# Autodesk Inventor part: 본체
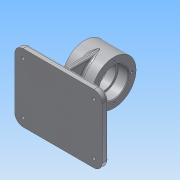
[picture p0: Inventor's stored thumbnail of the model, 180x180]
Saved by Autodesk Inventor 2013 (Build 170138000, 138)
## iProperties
Created: 2019-09
Part Number: 본체
Material: 알루미늄 6061
Document SubType Name: Modeling
Designer: Administrator
Density: 2.71 g/cm^3
Mass: 556.673 g
Surface Area: 495.884 cm^2
Volume: 205.414 cm^3
Author: Administrator
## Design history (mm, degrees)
sketch "스케치1"
  geometry: L1 (-21, 0)-(21, 0); L2 (-21, 0)-(-21, 32); L3 (-21, 32)-(21, 32); L4 (21, 32)-(21, 0); L5 (-21, 21)-(-6, 21); L6 (-6, 21)-(-6, 18); L7 (-6, 18)-(6, 18); L8 (6, 18)-(6, 21); L9 (6, 21)-(21, 21); L10 (-63, -50)-(63, -50); L11 (63, -50)-(63, -59); L12 (63, -59)-(-63, -59); L13 (-63, -59)-(-63, -50); 3 further points
  constraints: 26 end point, 6 perpendicular, 5 parallel, 2 coincident, 2 equal length, 2 horizontal, 2 midpoint, 2 point on line, 1 vertical alignment
  dimensions: "d0" = 64 diameter of L3 L1; "d2" = 42 diameter of L9 L1; "d3" = 36 diameter of L7 L1; "d4" = 15 distance of L5.start L5.end; "d5" = 42 distance of L2.end L3.end; "d6" = 9 distance of L10.end L11.end; "d7" = 59 distance from line of point (0, 0) L12; "d8" = 126 distance of L11.end L12.end
revolve "회전1" stored, may be unused: angle "d9" = 90 deg
extrude "돌출1" join sketch "스케치1" distance "d10" = 36; taper "d12" = 0 deg; dims "d11" = 62, "d13" = 0
sketch "스케치4"
  geometry: L1 (59, 68)-(67, 68); L2 (67, 68)-(67, 4); L3 (67, 4)-(59, 4); L4 (59, 4)-(59, 68); L5 (46, 40)-(80, 40); L6 (80, 40)-(80, 32); L7 (80, 32)-(46, 32); L8 (46, 32)-(46, 40); 5 further points
  constraints: 16 end point, 4 midpoint, 4 parallel, 2 horizontal, 2 horizontal alignment, 2 perpendicular, 2 vertical alignment
  dimensions: "d14" = 8 distance of L1.start L1.end; "d16" = 64 distance of L1.end L2.end; "d17" = 8 distance of L5.end L6.end; "d18" = 34 distance of L6.end L7.end
extrude "돌출2" join sketch "스케치4" stored distance "d19" = 36; taper "d20" = 0 deg
sketch "스케치5"
  geometry: C1 r 32 at (0, 0) reference; 1 further point
  constraints: 1 vertical alignment
  dimensions: "d21" = 26 distance of C1.centre point (0, 26)
hole "구멍1" sketch "스케치5" at (0, 26) diameter "d22" = 3.242; stored, may be unused: countersink angle "d26" = 90 deg, drill point angle "d28" = 118 deg; dims "d23" = 8, "d24" = 4, "d25" = 2, "d27" = 10
chamfer "모따기1" distance "d32" = 1; stored, may be unused: second distance "d33" = 2, angle "d34" = 45 deg
fillet "모깎기1" dims "d35" = 0.3
fillet "모깎기2" dims "d36" = 12
sketch "스케치6"
  geometry: A1 r 12 centre (0, 12) between (-12, 12) and (0, 0) reference; A2 r 12 centre (102, 12) between (102, 0) and (114, 12) reference; A3 r 12 centre (102, 86) between (114, 86) and (102, 98) reference; A4 r 12 centre (0, 86) between (0, 98) and (-12, 86) reference; 5 further points
  constraints: 4 coincident
hole "구멍2" sketch "스케치6" at (0, 12), (0, 86), (102, 86), (102, 12) diameter "d37" = 4.5; stored, may be unused: countersink angle "d41" = 90 deg, drill point angle "d43" = 118 deg; dims "d38" = 8, "d39" = 8, "d40" = 4.4, "d42" = 10
sketch "스케치7"
  geometry: L1 (114, 12)-(114, 86) reference; L2 (0, 98)-(102, 98) reference; 2 further points
  constraints: 1 other
  dimensions: "d44" = 63 distance from line of point (51, 88) L1; "d45" = 10 distance from line of point (51, 88) L2
feature "엠보싱1" sketch "스케치7" dims "d0" = 64, "d2" = 42, "d3" = 36, "d4" = 15, "d5" = 42, "d6" = 9, "d7" = 59, "d8" = 126, "d46" = 0.5, "d47" = 0
fillet "모깎기3" dims "d48" = 3
fillet "모깎기4" dims "d49" = 3
fillet "모깎기5" dims "d50" = 3
node "솔리드1"
pattern_circular "원형 패턴1" dims angle "d30" = 360 deg
mirror "대칭1"
